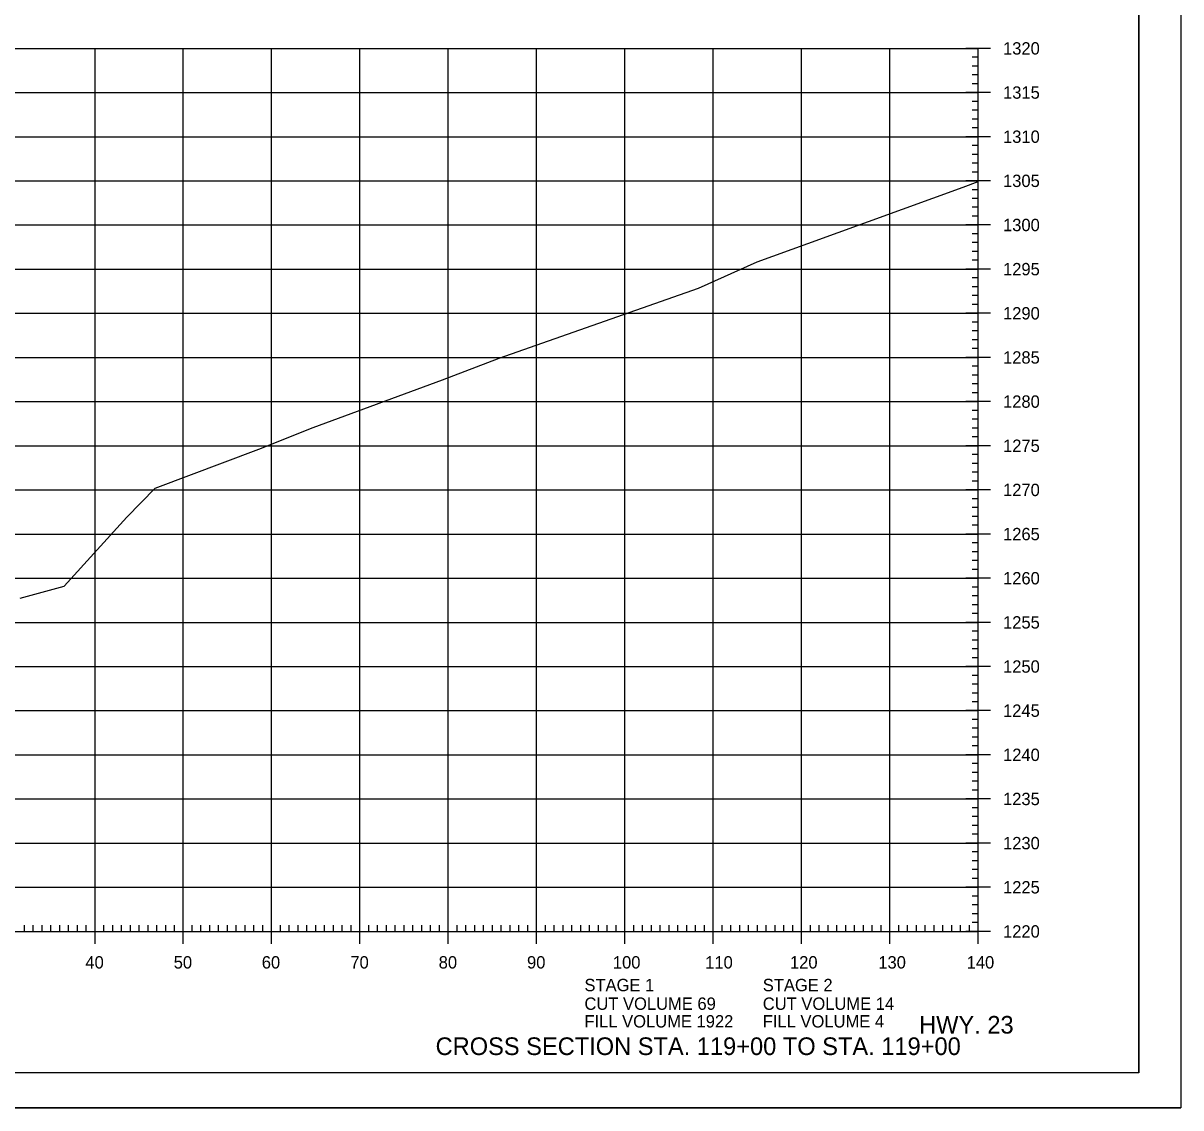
# Model space of a CAD drawing. Extents: x 1406028 to 1412453, y 321733 to 325986.
# Drawn here: x 1406621.8 to 1406752.8, y 324919.4 to 325042.2 of the extents above; entities that cross this region are included whole.
import ezdxf

# ---------------------------------------------------------------- set-up
doc = ezdxf.new("R2010")
doc.units = 0
for name, color, linetype in [('R_Axis', 7, 'Continuous'), ('R_Axis Annot', 7, 'Continuous'), ('R_Border', 7, 'Continuous'), ('R_Draft', 7, 'Continuous'), ('R_Exist Surface', 7, 'Continuous'), ('R_Grid', 7, 'Continuous'), ('R_No Plot', 7, 'Continuous')]:
    doc.layers.add(name, color=color, linetype=linetype)

msp = doc.modelspace()

# ---------------------------------------------------------------- linework, layer by layer
at = {"layer": 'R_Axis'}
for p, q in [((1406731.29, 325039.38), (1406728.49, 325039.38)), ((1406729.89, 324939.38), (1406729.89, 325039.38)), ((1406729.89, 325038.38), (1406729.19, 325038.38)), ((1406729.89, 325037.38), (1406729.19, 325037.38)), ((1406729.89, 325036.38), (1406729.19, 325036.38)), ((1406729.89, 325035.38), (1406729.19, 325035.38)), ((1406731.29, 325034.38), (1406728.49, 325034.38)), ((1406729.89, 325033.38), (1406729.19, 325033.38)), ((1406729.89, 325032.38), (1406729.19, 325032.38)), ((1406729.89, 325031.38), (1406729.19, 325031.38)), ((1406731.29, 325029.38), (1406728.49, 325029.38)), ((1406729.89, 325030.38), (1406729.19, 325030.38)), ((1406729.89, 325028.38), (1406729.19, 325028.38)), ((1406729.89, 325027.38), (1406729.19, 325027.38)), ((1406729.89, 325026.38), (1406729.19, 325026.38)), ((1406731.29, 325024.38), (1406728.49, 325024.38)), ((1406729.89, 325025.38), (1406729.19, 325025.38)), ((1406729.89, 325023.38), (1406729.19, 325023.38)), ((1406729.89, 325022.38), (1406729.19, 325022.38)), ((1406729.89, 325021.38), (1406729.19, 325021.38)), ((1406729.89, 325020.38), (1406729.19, 325020.38)), ((1406731.29, 325019.38), (1406728.49, 325019.38)), ((1406729.89, 325018.38), (1406729.19, 325018.38)), ((1406729.89, 325017.38), (1406729.19, 325017.38)), ((1406729.89, 325016.38), (1406729.19, 325016.38)), ((1406729.89, 325015.38), (1406729.19, 325015.38)), ((1406731.29, 325014.38), (1406728.49, 325014.38)), ((1406729.89, 325013.38), (1406729.19, 325013.38)), ((1406729.89, 325012.38), (1406729.19, 325012.38)), ((1406729.89, 325011.38), (1406729.19, 325011.38)), ((1406729.89, 325010.38), (1406729.19, 325010.38)), ((1406731.29, 325009.38), (1406728.49, 325009.38)), ((1406729.89, 325008.38), (1406729.19, 325008.38)), ((1406729.89, 325007.38), (1406729.19, 325007.38)), ((1406729.89, 325006.38), (1406729.19, 325006.38)), ((1406729.89, 325005.38), (1406729.19, 325005.38)), ((1406731.29, 325004.38), (1406728.49, 325004.38)), ((1406729.89, 325003.38), (1406729.19, 325003.38)), ((1406729.89, 325002.38), (1406729.19, 325002.38)), ((1406729.89, 325001.38), (1406729.19, 325001.38)), ((1406731.29, 324999.38), (1406728.49, 324999.38)), ((1406729.89, 325000.38), (1406729.19, 325000.38)), ((1406729.89, 324998.38), (1406729.19, 324998.38)), ((1406729.89, 324997.38), (1406729.19, 324997.38)), ((1406729.89, 324996.38), (1406729.19, 324996.38)), ((1406729.89, 324995.38), (1406729.19, 324995.38)), ((1406731.29, 324994.38), (1406728.49, 324994.38)), ((1406729.89, 324993.38), (1406729.19, 324993.38)), ((1406729.89, 324992.38), (1406729.19, 324992.38)), ((1406729.89, 324991.38), (1406729.19, 324991.38)), ((1406729.89, 324990.38), (1406729.19, 324990.38)), ((1406731.29, 324989.38), (1406728.49, 324989.38)), ((1406729.89, 324988.38), (1406729.19, 324988.38)), ((1406729.89, 324987.38), (1406729.19, 324987.38)), ((1406729.89, 324986.38), (1406729.19, 324986.38)), ((1406729.89, 324985.38), (1406729.19, 324985.38)), ((1406731.29, 324984.38), (1406728.49, 324984.38)), ((1406729.89, 324983.38), (1406729.19, 324983.38)), ((1406729.89, 324982.38), (1406729.19, 324982.38)), ((1406729.89, 324981.38), (1406729.19, 324981.38)), ((1406729.89, 324980.38), (1406729.19, 324980.38)), ((1406731.29, 324979.38), (1406728.49, 324979.38)), ((1406729.89, 324978.38), (1406729.19, 324978.38)), ((1406729.89, 324977.38), (1406729.19, 324977.38)), ((1406729.89, 324976.38), (1406729.19, 324976.38)), ((1406731.29, 324974.38), (1406728.49, 324974.38)), ((1406729.89, 324975.38), (1406729.19, 324975.38)), ((1406729.89, 324973.38), (1406729.19, 324973.38)), ((1406729.89, 324972.38), (1406729.19, 324972.38)), ((1406729.89, 324971.38), (1406729.19, 324971.38)), ((1406731.29, 324969.38), (1406728.49, 324969.38)), ((1406729.89, 324970.38), (1406729.19, 324970.38)), ((1406729.89, 324968.38), (1406729.19, 324968.38)), ((1406729.89, 324967.38), (1406729.19, 324967.38)), ((1406729.89, 324966.38), (1406729.19, 324966.38)), ((1406729.89, 324965.38), (1406729.19, 324965.38)), ((1406731.29, 324964.38), (1406728.49, 324964.38)), ((1406729.89, 324963.38), (1406729.19, 324963.38)), ((1406729.89, 324962.38), (1406729.19, 324962.38)), ((1406729.89, 324961.38), (1406729.19, 324961.38)), ((1406729.89, 324960.38), (1406729.19, 324960.38)), ((1406731.29, 324959.38), (1406728.49, 324959.38)), ((1406729.89, 324958.38), (1406729.19, 324958.38)), ((1406729.89, 324957.38), (1406729.19, 324957.38)), ((1406729.89, 324956.38), (1406729.19, 324956.38)), ((1406729.89, 324955.38), (1406729.19, 324955.38)), ((1406731.29, 324954.38), (1406728.49, 324954.38)), ((1406729.89, 324953.38), (1406729.19, 324953.38)), ((1406729.89, 324952.38), (1406729.19, 324952.38)), ((1406729.89, 324951.38), (1406729.19, 324951.38)), ((1406729.89, 324950.38), (1406729.19, 324950.38)), ((1406731.29, 324949.38), (1406728.49, 324949.38)), ((1406729.89, 324948.38), (1406729.19, 324948.38)), ((1406729.89, 324947.38), (1406729.19, 324947.38)), ((1406729.89, 324946.38), (1406729.19, 324946.38)), ((1406731.29, 324944.38), (1406728.49, 324944.38)), ((1406729.89, 324945.38), (1406729.19, 324945.38)), ((1406729.89, 324943.38), (1406729.19, 324943.38)), ((1406729.89, 324942.38), (1406729.19, 324942.38)), ((1406629.89, 324937.98), (1406629.89, 324940.78)), ((1406639.89, 324937.98), (1406639.89, 324940.78)), ((1406649.89, 324937.98), (1406649.89, 324940.78)), ((1406659.89, 324937.98), (1406659.89, 324940.78)), ((1406669.89, 324937.98), (1406669.89, 324940.78)), ((1406679.89, 324937.98), (1406679.89, 324940.78)), ((1406689.89, 324937.98), (1406689.89, 324940.78)), ((1406699.89, 324937.98), (1406699.89, 324940.78)), ((1406709.89, 324937.98), (1406709.89, 324940.78)), ((1406719.89, 324937.98), (1406719.89, 324940.78)), ((1406729.89, 324941.38), (1406729.19, 324941.38)), ((1406729.89, 324940.38), (1406729.19, 324940.38)), ((1406729.89, 324937.98), (1406729.89, 324940.78)), ((1406449.89, 324939.38), (1406729.89, 324939.38)), ((1406621.89, 324939.38), (1406621.89, 324940.08)), ((1406622.89, 324939.38), (1406622.89, 324940.08)), ((1406623.89, 324939.38), (1406623.89, 324940.08)), ((1406624.89, 324939.38), (1406624.89, 324940.08)), ((1406625.89, 324939.38), (1406625.89, 324940.08)), ((1406626.89, 324939.38), (1406626.89, 324940.08)), ((1406627.89, 324939.38), (1406627.89, 324940.08)), ((1406628.89, 324939.38), (1406628.89, 324940.08)), ((1406630.89, 324939.38), (1406630.89, 324940.08)), ((1406631.89, 324939.38), (1406631.89, 324940.08)), ((1406632.89, 324939.38), (1406632.89, 324940.08)), ((1406633.89, 324939.38), (1406633.89, 324940.08)), ((1406634.89, 324939.38), (1406634.89, 324940.08)), ((1406635.89, 324939.38), (1406635.89, 324940.08)), ((1406636.89, 324939.38), (1406636.89, 324940.08)), ((1406637.89, 324939.38), (1406637.89, 324940.08)), ((1406638.89, 324939.38), (1406638.89, 324940.08)), ((1406640.89, 324939.38), (1406640.89, 324940.08)), ((1406641.89, 324939.38), (1406641.89, 324940.08)), ((1406642.89, 324939.38), (1406642.89, 324940.08)), ((1406643.89, 324939.38), (1406643.89, 324940.08)), ((1406644.89, 324939.38), (1406644.89, 324940.08)), ((1406645.89, 324939.38), (1406645.89, 324940.08)), ((1406646.89, 324939.38), (1406646.89, 324940.08)), ((1406647.89, 324939.38), (1406647.89, 324940.08)), ((1406648.89, 324939.38), (1406648.89, 324940.08)), ((1406650.89, 324939.38), (1406650.89, 324940.08)), ((1406651.89, 324939.38), (1406651.89, 324940.08)), ((1406652.89, 324939.38), (1406652.89, 324940.08)), ((1406653.89, 324939.38), (1406653.89, 324940.08)), ((1406654.89, 324939.38), (1406654.89, 324940.08)), ((1406655.89, 324939.38), (1406655.89, 324940.08)), ((1406656.89, 324939.38), (1406656.89, 324940.08)), ((1406657.89, 324939.38), (1406657.89, 324940.08)), ((1406658.89, 324939.38), (1406658.89, 324940.08)), ((1406660.89, 324939.38), (1406660.89, 324940.08)), ((1406661.89, 324939.38), (1406661.89, 324940.08)), ((1406662.89, 324939.38), (1406662.89, 324940.08)), ((1406663.89, 324939.38), (1406663.89, 324940.08)), ((1406664.89, 324939.38), (1406664.89, 324940.08)), ((1406665.89, 324939.38), (1406665.89, 324940.08)), ((1406666.89, 324939.38), (1406666.89, 324940.08)), ((1406667.89, 324939.38), (1406667.89, 324940.08)), ((1406668.89, 324939.38), (1406668.89, 324940.08)), ((1406670.89, 324939.38), (1406670.89, 324940.08)), ((1406671.89, 324939.38), (1406671.89, 324940.08)), ((1406672.89, 324939.38), (1406672.89, 324940.08)), ((1406673.89, 324939.38), (1406673.89, 324940.08)), ((1406674.89, 324939.38), (1406674.89, 324940.08)), ((1406675.89, 324939.38), (1406675.89, 324940.08)), ((1406676.89, 324939.38), (1406676.89, 324940.08)), ((1406677.89, 324939.38), (1406677.89, 324940.08)), ((1406678.89, 324939.38), (1406678.89, 324940.08)), ((1406680.89, 324939.38), (1406680.89, 324940.08)), ((1406681.89, 324939.38), (1406681.89, 324940.08)), ((1406682.89, 324939.38), (1406682.89, 324940.08)), ((1406683.89, 324939.38), (1406683.89, 324940.08)), ((1406684.89, 324939.38), (1406684.89, 324940.08)), ((1406685.89, 324939.38), (1406685.89, 324940.08)), ((1406686.89, 324939.38), (1406686.89, 324940.08)), ((1406687.89, 324939.38), (1406687.89, 324940.08)), ((1406688.89, 324939.38), (1406688.89, 324940.08)), ((1406690.89, 324939.38), (1406690.89, 324940.08)), ((1406691.89, 324939.38), (1406691.89, 324940.08)), ((1406692.89, 324939.38), (1406692.89, 324940.08)), ((1406693.89, 324939.38), (1406693.89, 324940.08)), ((1406694.89, 324939.38), (1406694.89, 324940.08)), ((1406695.89, 324939.38), (1406695.89, 324940.08)), ((1406696.89, 324939.38), (1406696.89, 324940.08)), ((1406697.89, 324939.38), (1406697.89, 324940.08)), ((1406698.89, 324939.38), (1406698.89, 324940.08)), ((1406700.89, 324939.38), (1406700.89, 324940.08)), ((1406701.89, 324939.38), (1406701.89, 324940.08)), ((1406702.89, 324939.38), (1406702.89, 324940.08)), ((1406703.89, 324939.38), (1406703.89, 324940.08)), ((1406704.89, 324939.38), (1406704.89, 324940.08)), ((1406705.89, 324939.38), (1406705.89, 324940.08)), ((1406706.89, 324939.38), (1406706.89, 324940.08)), ((1406707.89, 324939.38), (1406707.89, 324940.08)), ((1406708.89, 324939.38), (1406708.89, 324940.08)), ((1406710.89, 324939.38), (1406710.89, 324940.08)), ((1406711.89, 324939.38), (1406711.89, 324940.08)), ((1406712.89, 324939.38), (1406712.89, 324940.08)), ((1406713.89, 324939.38), (1406713.89, 324940.08)), ((1406714.89, 324939.38), (1406714.89, 324940.08)), ((1406715.89, 324939.38), (1406715.89, 324940.08)), ((1406716.89, 324939.38), (1406716.89, 324940.08)), ((1406717.89, 324939.38), (1406717.89, 324940.08)), ((1406718.89, 324939.38), (1406718.89, 324940.08)), ((1406720.89, 324939.38), (1406720.89, 324940.08)), ((1406721.89, 324939.38), (1406721.89, 324940.08)), ((1406722.89, 324939.38), (1406722.89, 324940.08)), ((1406723.89, 324939.38), (1406723.89, 324940.08)), ((1406724.89, 324939.38), (1406724.89, 324940.08)), ((1406725.89, 324939.38), (1406725.89, 324940.08)), ((1406726.89, 324939.38), (1406726.89, 324940.08)), ((1406727.89, 324939.38), (1406727.89, 324940.08)), ((1406731.29, 324939.38), (1406728.49, 324939.38)), ((1406728.89, 324939.38), (1406728.89, 324940.08))]:
    msp.add_line(p, q, dxfattribs=at)
at = {"layer": 'R_Border'}
for q in [(1406748.07, 325128.84), (1406431.89, 324923.38)]:
    msp.add_line((1406748.07, 324923.38), q, dxfattribs=at)
at = {"layer": 'R_Exist Surface'}
msp.add_lwpolyline([(1406621.43, 324977.12), (1406626.4, 324978.46), (1406633.48, 324986.28), (1406636.7, 324989.58), (1406648.45, 324994), (1406654.6, 324996.43), (1406669.23, 325001.83), (1406675.63, 325004.31), (1406679.83, 325005.78), (1406698.22, 325012.24), (1406704.86, 325015.2), (1406710.58, 325017.3), (1406728.18, 325023.65), (1406729.89, 325024.29)], dxfattribs=at)
at = {"layer": 'R_Grid'}
for p, q in [((1406449.89, 325039.38), (1406729.89, 325039.38)), ((1406629.89, 324939.38), (1406629.89, 325039.38)), ((1406639.89, 324939.38), (1406639.89, 325039.38)), ((1406649.89, 324939.38), (1406649.89, 325039.38)), ((1406659.89, 324939.38), (1406659.89, 325039.38)), ((1406669.89, 324939.38), (1406669.89, 325039.38)), ((1406679.89, 324939.38), (1406679.89, 325039.38)), ((1406689.89, 324939.38), (1406689.89, 325039.38)), ((1406699.89, 324939.38), (1406699.89, 325039.38)), ((1406709.89, 324939.38), (1406709.89, 325039.38)), ((1406719.89, 324939.38), (1406719.89, 325039.38)), ((1406729.89, 324939.38), (1406729.89, 325039.38)), ((1406449.89, 325034.38), (1406729.89, 325034.38)), ((1406449.89, 325029.38), (1406729.89, 325029.38)), ((1406449.89, 325024.38), (1406729.89, 325024.38)), ((1406449.89, 325019.38), (1406729.89, 325019.38)), ((1406449.89, 325014.38), (1406729.89, 325014.38)), ((1406449.89, 325009.38), (1406729.89, 325009.38)), ((1406449.89, 325004.38), (1406729.89, 325004.38)), ((1406449.89, 324999.38), (1406729.89, 324999.38)), ((1406449.89, 324994.38), (1406729.89, 324994.38)), ((1406449.89, 324989.38), (1406729.89, 324989.38)), ((1406449.89, 324984.38), (1406729.89, 324984.38)), ((1406449.89, 324979.38), (1406729.89, 324979.38)), ((1406449.89, 324974.38), (1406729.89, 324974.38)), ((1406449.89, 324969.38), (1406729.89, 324969.38)), ((1406449.89, 324964.38), (1406729.89, 324964.38)), ((1406449.89, 324959.38), (1406729.89, 324959.38)), ((1406449.89, 324954.38), (1406729.89, 324954.38)), ((1406449.89, 324949.38), (1406729.89, 324949.38)), ((1406449.89, 324944.38), (1406729.89, 324944.38)), ((1406449.89, 324939.38), (1406729.89, 324939.38))]:
    msp.add_line(p, q, dxfattribs=at)
at = {"layer": 'R_No Plot'}
msp.add_line((1406419.49, 324919.4), (1406752.82, 324919.4), dxfattribs=at)
for points in [[(1406419.48, 325132.74), (1406752.82, 325132.74), (1406752.82, 324919.4), (1406419.48, 324919.4)], [(1406665.81, 325128.84), (1406685.43, 325128.84), (1406685.43, 325118.96), (1406701.54, 325118.96), (1406724.74, 325118.96), (1406724.74, 325094.63), (1406748.07, 325094.63), (1406748.07, 324923.38), (1406431.89, 324923.38), (1406431.89, 325128.84)]]:
    msp.add_lwpolyline(points, close=True, dxfattribs=at)

# ---------------------------------------------------------------- texts
at = {"layer": 'R_Axis Annot'}
for s, p in [('1320', (1406732.69, 325038.68)), ('1315', (1406732.69, 325033.68)), ('1310', (1406732.69, 325028.68)), ('1305', (1406732.69, 325023.68)), ('1300', (1406732.69, 325018.68)), ('1295', (1406732.69, 325013.68)), ('1290', (1406732.69, 325008.68)), ('1285', (1406732.69, 325003.68)), ('1280', (1406732.69, 324998.68)), ('1275', (1406732.69, 324993.68)), ('1270', (1406732.69, 324988.68)), ('1265', (1406732.69, 324983.68)), ('1260', (1406732.69, 324978.68)), ('1255', (1406732.69, 324973.68)), ('1250', (1406732.69, 324968.68)), ('1245', (1406732.69, 324963.68)), ('1240', (1406732.69, 324958.68)), ('1235', (1406732.69, 324953.68)), ('1230', (1406732.69, 324948.68)), ('1225', (1406732.69, 324943.68)), ('1220', (1406732.69, 324938.68)), ('40', (1406628.8, 324935.18)), ('50', (1406638.8, 324935.18)), ('60', (1406648.77, 324935.18)), ('70', (1406658.8, 324935.18)), ('80', (1406668.8, 324935.18)), ('90', (1406678.8, 324935.18)), ('100', (1406688.52, 324935.18)), ('110', (1406698.97, 324935.18)), ('120', (1406708.57, 324935.18)), ('130', (1406718.57, 324935.18)), ('140', (1406728.57, 324935.18)), ('STAGE 1', (1406685.3, 324932.61)), ('STAGE 2', (1406705.49, 324932.61)), ('CUT VOLUME 69', (1406685.3, 324930.5)), ('CUT VOLUME 14', (1406705.49, 324930.5)), ('FILL VOLUME 1922', (1406685.3, 324928.5)), ('FILL VOLUME 4', (1406705.49, 324928.5))]:
    msp.add_text(s, height=1.4, dxfattribs=at).set_placement(p)
at = {"layer": 'R_Draft'}
for s, p in [('HWY. 23', (1406723.19, 324927.81)), ('CROSS SECTION STA. 119+00 TO STA. 119+00', (1406668.45, 324925.38))]:
    msp.add_text(s, height=2, dxfattribs=at).set_placement(p)
at = {"layer": 'R_No Plot'}
for p in [(1406710.53, 325017.25), (1406698.18, 325012.19), (1406675.59, 325004.26), (1406654.56, 324996.38), (1406636.65, 324989.53), (1406626.35, 324978.41)]:
    msp.add_text('+', height=0.1, dxfattribs=at).set_placement(p)

doc.saveas('drawing.dxf')
